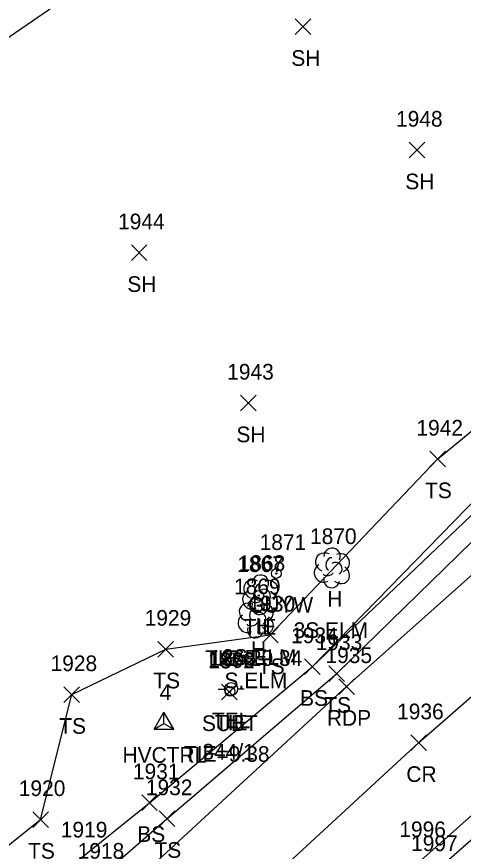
# Model space of a CAD drawing. Extents: x 1459992 to 1461532, y 647785 to 648535.
# Drawn here: x 1461290.9 to 1461347.9, y 648356.5 to 648463.1 of the extents above; entities that cross this region are included whole.
import ezdxf

# ---------------------------------------------------------------- set-up
doc = ezdxf.new("R2010")
doc.units = 0
for name, color, linetype in [('C_A', 7, 'Continuous'), ('C_C', 7, 'Continuous'), ('C_I', 7, 'Continuous'), ('CBP', 7, 'Continuous'), ('CPSM', 7, 'Continuous'), ('L_A', 7, 'Continuous'), ('L_C', 7, 'Continuous'), ('L_I', 7, 'Continuous'), ('L_TIC', 7, 'Continuous'), ('LELB', 7, 'Continuous'), ('LSOGP', 7, 'Continuous'), ('LTD', 7, 'Continuous'), ('P_A', 7, 'Continuous'), ('P_I', 7, 'Continuous'), ('P_TIC', 7, 'Continuous'), ('PET', 7, 'Continuous'), ('PRC', 7, 'Continuous'), ('U_A', 7, 'Continuous'), ('U_C', 7, 'Continuous'), ('U_I', 7, 'Continuous'), ('U_TIC', 7, 'Continuous'), ('UP', 7, 'Continuous'), ('UPGW', 7, 'Continuous')]:
    doc.layers.add(name, color=color, linetype=linetype)

msp = doc.modelspace()

# ---------------------------------------------------------------- linework, layer by layer
at = {"layer": 'CBP'}
for centre, radius in [((1461321.79, 648389.18), 0.625), ((1461321.79, 648389.18), 0.0833), ((1461318.12, 648376.94), 0.625), ((1461318.12, 648376.94), 0.0833)]:
    msp.add_circle(centre, radius, dxfattribs=at)
at = {"layer": 'CPSM'}
for p, q in [((1461308.44, 648372.1), (1461309.69, 648374.26)), ((1461310.94, 648372.1), (1461309.69, 648374.26)), ((1461309.69, 648372.82), (1461309.69, 648374.26)), ((1461308.44, 648372.1), (1461309.69, 648372.82)), ((1461308.44, 648372.1), (1461310.94, 648372.1)), ((1461309.69, 648372.82), (1461309.69, 648372.82)), ((1461309.69, 648372.82), (1461310.94, 648372.1))]:
    msp.add_line(p, q, dxfattribs=at)
at = {"layer": 'L_TIC'}
for points in [[(1461326.47, 648460.81), (1461328.47, 648462.81)], [(1461328.47, 648460.81), (1461326.47, 648462.81)], [(1461341.03, 648445.05), (1461343.03, 648447.05)], [(1461343.03, 648445.05), (1461341.03, 648447.05)], [(1461305.52, 648431.94), (1461307.52, 648433.94)], [(1461307.52, 648431.94), (1461305.52, 648433.94)], [(1461319.46, 648412.75), (1461321.46, 648414.75)], [(1461321.46, 648412.75), (1461319.46, 648414.75)], [(1461343.65, 648405.6), (1461345.65, 648407.6)], [(1461345.65, 648405.6), (1461343.65, 648407.6)], [(1461322.28, 648383.14), (1461324.28, 648385.14)], [(1461324.28, 648383.14), (1461322.28, 648385.14)], [(1461308.92, 648381.32), (1461310.92, 648383.32)], [(1461310.92, 648381.32), (1461308.92, 648383.32)], [(1461327.64, 648379.09), (1461329.64, 648381.09)], [(1461329.64, 648379.09), (1461327.64, 648381.09)], [(1461327.64, 648379.09), (1461329.64, 648381.09)], [(1461329.64, 648379.09), (1461327.64, 648381.09)], [(1461330.77, 648378.2), (1461332.77, 648380.2)], [(1461332.77, 648378.2), (1461330.77, 648380.2)], [(1461296.9, 648375.52), (1461298.9, 648377.52)], [(1461298.9, 648375.52), (1461296.9, 648377.52)], [(1461306.84, 648361.71), (1461308.84, 648363.71)], [(1461308.84, 648361.71), (1461306.84, 648363.71)], [(1461292.92, 648359.57), (1461294.92, 648361.57)], [(1461294.92, 648359.57), (1461292.92, 648361.57)], [(1461309.07, 648359.68), (1461311.07, 648361.68)], [(1461311.07, 648359.68), (1461309.07, 648361.68)]]:
    msp.add_lwpolyline(points, dxfattribs=at)
at = {"layer": 'LELB'}
for points in [[(1461053.3, 648342.88), (1461057.1, 648347.56), (1461103.6, 648329.25), (1461132.09, 648319.28), (1461156.26, 648311.83), (1461179.8, 648313.29), (1461203.15, 648318.77), (1461223.06, 648334.41), (1461252.96, 648329.42), (1461275.76, 648346.01), (1461293.92, 648360.57), (1461297.9, 648376.52), (1461309.92, 648382.32), (1461323.28, 648384.14), (1461344.65, 648406.6), (1461362.09, 648421.03), (1461389.72, 648443.02), (1461411.96, 648455.77)], [(1461328.64, 648380.09), (1461350.05, 648402.05), (1461365.91, 648415.34), (1461392.09, 648437.54), (1461414.11, 648452.02)], [(1461045.75, 648345.16), (1461053.3, 648342.88), (1461099.57, 648323.3), (1461128.93, 648312.14), (1461154.02, 648304.18), (1461179.99, 648301.37), (1461204.48, 648303), (1461231.37, 648312.49), (1461255.41, 648321.87), (1461278.91, 648340.15), (1461298.64, 648355.28), (1461307.84, 648362.71), (1461328.64, 648380.09), (1461350.69, 648401.06), (1461366.77, 648414.15), (1461392.6, 648435.99), (1461415.7, 648449.6)], [(1460952.34, 648377.13), (1460985.69, 648362.66), (1461027.43, 648346.63), (1461054.39, 648335.28), (1461097.58, 648319.81), (1461127.3, 648308.18), (1461153.51, 648301.33), (1461179.78, 648297.83), (1461204.84, 648300.47), (1461233.15, 648308.09), (1461257.01, 648318.59), (1461281.51, 648336.52), (1461300.79, 648352.57), (1461310.07, 648360.68), (1461331.77, 648379.2), (1461352.47, 648399.38), (1461367.35, 648413.21), (1461394.44, 648433.89), (1461417.38, 648445.8)], [(1461437.89, 648410.49), (1461418.94, 648407.67), (1461409.62, 648403.83), (1461397.12, 648398.78), (1461381.61, 648386.31), (1461361.68, 648369.15), (1461343.97, 648353.54), (1461325.1, 648333.83), (1461318.7, 648322.25), (1461308.65, 648307.17), (1461301.59, 648300.07), (1461298.1, 648291.15), (1461293.27, 648263.28), (1461293.55, 648252.72), (1461292.9, 648243.51), (1461295.99, 648233.83), (1461296.73, 648225.48), (1461296.73, 648222.49)]]:
    msp.add_lwpolyline(points, dxfattribs=at)
at = {"layer": 'LSOGP'}
msp.add_lwpolyline([(1461424.86, 648433.53), (1461418.97, 648443.38), (1461417.38, 648445.8), (1461415.7, 648449.6), (1461414.11, 648452.02), (1461411.96, 648455.77), (1461407.13, 648464.37), (1461399.06, 648478.69), (1461388.86, 648495.69), (1461378.34, 648513.06), (1461354.54, 648501.82), (1461314.28, 648477.24), (1461287.25, 648458.7)], dxfattribs=at)
at = {"layer": 'LTD'}
for p, q in [((1461331.13, 648392.75), (1461331.13, 648392.75)), ((1461331.13, 648392.75), (1461331.13, 648392.75)), ((1461321.97, 648389.32), (1461321.97, 648389.32)), ((1461321.97, 648389.32), (1461321.97, 648389.32)), ((1461321.39, 648386.34), (1461321.39, 648386.34)), ((1461321.39, 648386.34), (1461321.39, 648386.34))]:
    msp.add_line(p, q, dxfattribs=at)
for centre in [(1461331.17, 648394.18), (1461322.02, 648390.75), (1461321.44, 648387.78)]:
    msp.add_arc(centre, 1.05, 335.5272, 180.9563, dxfattribs=at)
for centre, major_axis, ratio, start_param, end_param in [((1461330.33, 648393.41), (1.21, -0.51), 0.895232, 1.570796, 4.712389), ((1461332.17, 648393.33), (-1.14, -0.48), 0.949671, 1.570796, 4.712389), ((1461330.92, 648393.2), (-0.208, -0.792), 0.645439, 3.141593, 6.283185), ((1461331.63, 648392.58), (-0.5, 0.667), 0.989748, 3.141593, 6.283185), ((1461330.04, 648392.04), (0.58, -1.04), 0.959034, 3.141593, 6.283185), ((1461332.13, 648391.91), (-1.09, 0.79), 0.841452, 1.570796, 4.712389), ((1461321.18, 648389.98), (1.21, -0.51), 0.895232, 1.570796, 4.712389), ((1461323.02, 648389.9), (-1.14, -0.48), 0.949671, 1.570796, 4.712389), ((1461331.13, 648391.25), (0.26, 1.06), 0.942809, 1.570796, 4.712389), ((1461330.67, 648392), (-0.625, -0.083), 0.423636, 0, 3.141593), ((1461321.77, 648389.78), (-0.208, -0.792), 0.645439, 3.141593, 6.283185), ((1461322.47, 648389.15), (-0.5, 0.667), 0.989748, 3.141593, 6.283185), ((1461320.89, 648388.61), (0.58, -1.04), 0.959034, 3.141593, 6.283185), ((1461322.97, 648388.49), (-1.09, 0.79), 0.841452, 1.570796, 4.712389), ((1461320.6, 648387.01), (1.21, -0.51), 0.895232, 1.570796, 4.712389), ((1461321.97, 648387.82), (0.26, 1.06), 0.942809, 1.570796, 4.712389), ((1461321.52, 648388.57), (-0.625, -0.083), 0.423636, 0, 3.141593), ((1461322.43, 648386.93), (-1.14, -0.48), 0.949671, 1.570796, 4.712389), ((1461321.18, 648386.8), (-0.208, -0.792), 0.645439, 3.141593, 6.283185), ((1461321.89, 648386.18), (-0.5, 0.667), 0.989748, 3.141593, 6.283185), ((1461320.31, 648385.63), (0.58, -1.04), 0.959034, 3.141593, 6.283185), ((1461322.39, 648385.51), (-1.09, 0.79), 0.841452, 1.570796, 4.712389), ((1461321.39, 648384.84), (0.26, 1.06), 0.942809, 1.570796, 4.712389), ((1461320.93, 648385.59), (-0.625, -0.083), 0.423636, 0, 3.141593)]:
    msp.add_ellipse(centre, major_axis=major_axis, ratio=ratio, start_param=start_param, end_param=end_param, dxfattribs=at)
at = {"layer": 'P_TIC'}
for points in [[(1461332.02, 648376.55), (1461334.02, 648378.55)], [(1461334.02, 648376.55), (1461332.02, 648378.55)], [(1461341.22, 648369.37), (1461343.22, 648371.37)], [(1461343.22, 648369.37), (1461341.22, 648371.37)]]:
    msp.add_lwpolyline(points, dxfattribs=at)
at = {"layer": 'PET'}
for points in [[(1460950.93, 648374.58), (1460984.69, 648360.32), (1461025.42, 648343.73), (1461053.38, 648332.51), (1461095.05, 648316.17), (1461126.17, 648304.95), (1461152.62, 648298.48), (1461179.86, 648295.54), (1461205.35, 648297.28), (1461234.43, 648304.94), (1461258.07, 648315.7), (1461283.68, 648333.5), (1461302.87, 648349.75), (1461333.02, 648377.55), (1461355.02, 648397.13), (1461371.06, 648410.57), (1461396.62, 648429.43), (1461418.97, 648443.38)], [(1461431.71, 648423.56), (1461406.61, 648408.47), (1461395.32, 648400.74), (1461379.71, 648387.97), (1461360, 648370.89), (1461342.5, 648355.32), (1461322.76, 648336.16), (1461306.54, 648318.18), (1461292.23, 648305.65), (1461275.7, 648293.86), (1461255.23, 648282.83), (1461238.6, 648275.7), (1461226.2, 648272.49), (1461213.09, 648269.85), (1461197.04, 648267.63), (1461176.94, 648267.36), (1461164.21, 648269.58)]]:
    msp.add_lwpolyline(points, dxfattribs=at)
at = {"layer": 'PRC'}
msp.add_lwpolyline([(1460946.83, 648364.55), (1460979.81, 648350.87), (1461020.89, 648333.41), (1461048.05, 648322.3), (1461089.53, 648305.67), (1461120.42, 648294.12), (1461149.17, 648286), (1461180.56, 648282.29), (1461207.18, 648283.7), (1461238.84, 648291.79), (1461263.78, 648303.51), (1461290.77, 648322.92), (1461310.31, 648340.94), (1461342.22, 648370.37), (1461365.17, 648390.4), (1461371.57, 648396.04), (1461402.62, 648419.98), (1461424.86, 648433.53)], dxfattribs=at)
at = {"layer": 'U_TIC'}
for points in [[(1461317.05, 648375.87), (1461319.05, 648377.87)], [(1461319.05, 648375.87), (1461317.05, 648377.87)]]:
    msp.add_lwpolyline(points, dxfattribs=at)
at = {"layer": 'UP'}
for p, q in [((1461316.61, 648377.23), (1461317.43, 648377.23)), ((1461318.27, 648377.23), (1461318.27, 648377.23)), ((1461319.93, 648377.23), (1461319.1, 648377.23)), ((1461319.1, 648377.23), (1461319.1, 648377.23)), ((1461319.93, 648377.23), (1461319.93, 648377.23))]:
    msp.add_line(p, q, dxfattribs=at)
msp.add_circle((1461318.27, 648377.23), 0.833, dxfattribs=at)
at = {"layer": 'UPGW'}
for radius in [0.625, 0.0833]:
    msp.add_circle((1461324.04, 648391.99), radius, dxfattribs=at)

# ---------------------------------------------------------------- texts
at = {"layer": 'C_A'}
for s, p in [('TIE', (1461319.87, 648384.18)), ('TIE', (1461316.2, 648371.94)), ('HVCTRL', (1461304.39, 648367.82))]:
    msp.add_text(s, height=2, dxfattribs=at).set_placement(p)
at = {"layer": 'C_C'}
for s, p in [('TIE=20.34', (1461314.94, 648380.18)), ('TIE=9.38', (1461312.25, 648367.94))]:
    msp.add_text(s, height=2, dxfattribs=at).set_placement(p)
at = {"layer": 'C_I'}
for s, p in [('1867', (1461319.05, 648392.18)), ('1866', (1461315.33, 648379.94)), ('4', (1461309.13, 648375.82))]:
    msp.add_text(s, height=2, dxfattribs=at).set_placement(p)
at = {"layer": 'L_A'}
for s, p in [('SH', (1461325.96, 648456.81)), ('SH', (1461340.52, 648441.05)), ('SH', (1461305.01, 648427.94)), ('SH', (1461318.95, 648408.75)), ('TS', (1461343.05, 648401.6)), ('H', (1461330.56, 648387.75)), ('H', (1461321.41, 648384.32)), ('H', (1461320.82, 648381.34)), ('TS', (1461321.69, 648379.14)), ('TS', (1461308.33, 648377.32)), ('BS', (1461327.08, 648375.09)), ('BS', (1461327.08, 648375.09)), ('TS', (1461330.18, 648374.2)), ('TS', (1461296.31, 648371.52)), ('BS', (1461306.28, 648357.71)), ('TS', (1461292.33, 648355.57)), ('TS', (1461308.48, 648355.68))]:
    msp.add_text(s, height=2, dxfattribs=at).set_placement(p)
at = {"layer": 'L_C'}
for s, p in [('3S.ELM', (1461326.26, 648383.75)), ('2S.ELM', (1461317.11, 648380.32)), ('S.ELM', (1461317.42, 648377.34))]:
    msp.add_text(s, height=2, dxfattribs=at).set_placement(p)
at = {"layer": 'L_I'}
for s, p in [('1948', (1461339.34, 648449.05)), ('1944', (1461303.83, 648435.94)), ('1943', (1461317.77, 648416.75)), ('1942', (1461341.95, 648409.6)), ('1870', (1461328.35, 648395.75)), ('1868', (1461319.23, 648392.32)), ('1869', (1461318.64, 648389.34)), ('1930', (1461320.5, 648387.14)), ('1929', (1461307.22, 648385.32)), ('1934', (1461325.94, 648383.09)), ('1934', (1461325.94, 648383.09)), ('1933', (1461329.08, 648382.2)), ('1928', (1461295.2, 648379.52)), ('1931', (1461305.72, 648365.71)), ('1920', (1461291.14, 648363.57)), ('1932', (1461307.38, 648363.68)), ('1919', (1461296.51, 648358.28)), ('1997', (1461341.27, 648356.54)), ('1918', (1461298.66, 648355.57))]:
    msp.add_text(s, height=2, dxfattribs=at).set_placement(p)
at = {"layer": 'P_A'}
for s, p in [('RDP', (1461330.51, 648372.55)), ('CR', (1461340.66, 648365.37))]:
    msp.add_text(s, height=2, dxfattribs=at).set_placement(p)
at = {"layer": 'P_I'}
for s, p in [('1935', (1461330.33, 648380.55)), ('1936', (1461339.48, 648373.37)), ('1996', (1461339.76, 648358.32))]:
    msp.add_text(s, height=2, dxfattribs=at).set_placement(p)
at = {"layer": 'U_A'}
for s, p in [('GUYW', (1461320.43, 648386.99)), ('TEL', (1461315.83, 648372.23)), ('SUBT', (1461314.54, 648371.87))]:
    msp.add_text(s, height=2, dxfattribs=at).set_placement(p)
at = {"layer": 'U_C'}
msp.add_text('344/1', height=2, dxfattribs=at).set_placement((1461314.6, 648368.23))
at = {"layer": 'U_I'}
for s, p in [('1871', (1461321.91, 648394.99)), ('1872', (1461315.35, 648379.87)), ('1865', (1461315.53, 648380.23))]:
    msp.add_text(s, height=2, dxfattribs=at).set_placement(p)

doc.saveas('drawing.dxf')
